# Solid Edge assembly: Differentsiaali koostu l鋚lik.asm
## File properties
Author: Türk
Template: Iso Assembly.asm
Last saved by: Türk
Revision: 18
Application: Solid Edge
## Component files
diffri korpus.par
Differentsiaali koostu.asm
ikehammakas.par
Kuullaager Tagu.asm
polt.par
diffri korpus_mir1.par
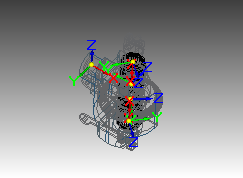
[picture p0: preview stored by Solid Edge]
